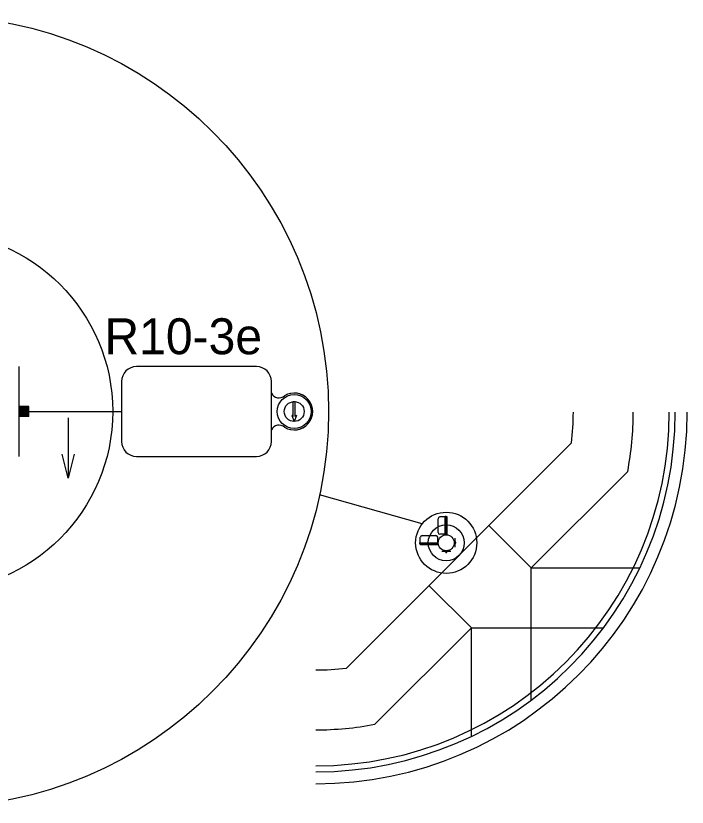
# Model space of a CAD drawing. Extents: x 1695551 to 1695718, y 544410 to 544516.
# Drawn here: x 1695680.98 to 1695694.99, y 544457.81 to 544474.32 of the extents above; entities that cross this region are included whole.
import ezdxf

# ---------------------------------------------------------------- set-up
doc = ezdxf.new("R2010")
doc.units = 0
doc.layers.add('T_Drafting', color=7, linetype='Continuous')

msp = doc.modelspace()

# ---------------------------------------------------------------- linework, layer by layer
at = {"layer": 'T_Drafting'}
for p, q in [((1695681.044, 544467.004), (1695681.044, 544465.129)), ((1695686.003, 544467.004), (1695683.499, 544467.004)), ((1695683.186, 544466.691), (1695683.186, 544465.441)), ((1695686.315, 544465.441), (1695686.315, 544466.691)), ((1695686.771, 544466.273), (1695686.809, 544466.273)), ((1695686.771, 544465.96), (1695686.771, 544466.273)), ((1695686.809, 544465.96), (1695686.809, 544466.273)), ((1695681.252, 544466.171), (1695681.044, 544466.171)), ((1695681.044, 544465.963), (1695681.251, 544466.171)), ((1695681.044, 544465.967), (1695681.248, 544466.171)), ((1695681.044, 544465.97), (1695681.244, 544466.171)), ((1695681.044, 544465.974), (1695681.241, 544466.171)), ((1695681.044, 544465.977), (1695681.237, 544466.171)), ((1695681.044, 544465.981), (1695681.234, 544466.171)), ((1695681.044, 544465.984), (1695681.23, 544466.171)), ((1695681.044, 544465.988), (1695681.227, 544466.171)), ((1695681.044, 544465.991), (1695681.223, 544466.171)), ((1695681.044, 544465.995), (1695681.22, 544466.171)), ((1695681.044, 544465.998), (1695681.216, 544466.171)), ((1695681.044, 544466.002), (1695681.213, 544466.171)), ((1695681.044, 544466.005), (1695681.209, 544466.171)), ((1695681.044, 544466.009), (1695681.205, 544466.171)), ((1695681.044, 544466.013), (1695681.202, 544466.171)), ((1695681.044, 544466.016), (1695681.198, 544466.171)), ((1695681.044, 544466.02), (1695681.195, 544466.171)), ((1695681.044, 544466.023), (1695681.191, 544466.171)), ((1695681.044, 544466.027), (1695681.188, 544466.171)), ((1695681.044, 544466.03), (1695681.184, 544466.171)), ((1695681.044, 544466.034), (1695681.181, 544466.171)), ((1695681.044, 544466.037), (1695681.177, 544466.171)), ((1695681.044, 544466.041), (1695681.174, 544466.171)), ((1695681.044, 544466.044), (1695681.17, 544466.171)), ((1695681.044, 544466.048), (1695681.167, 544466.171)), ((1695681.044, 544466.051), (1695681.163, 544466.171)), ((1695681.044, 544466.055), (1695681.16, 544466.171)), ((1695681.044, 544466.058), (1695681.156, 544466.171)), ((1695681.044, 544466.062), (1695681.152, 544466.171)), ((1695681.044, 544466.066), (1695681.149, 544466.171)), ((1695681.044, 544466.069), (1695681.145, 544466.171)), ((1695681.044, 544466.073), (1695681.142, 544466.171)), ((1695681.044, 544466.076), (1695681.138, 544466.171)), ((1695681.044, 544466.08), (1695681.135, 544466.171)), ((1695681.044, 544466.083), (1695681.131, 544466.171)), ((1695681.044, 544466.087), (1695681.128, 544466.171)), ((1695681.044, 544466.09), (1695681.124, 544466.171)), ((1695681.044, 544466.094), (1695681.121, 544466.171)), ((1695681.044, 544466.097), (1695681.117, 544466.171)), ((1695681.044, 544466.101), (1695681.114, 544466.171)), ((1695681.044, 544466.104), (1695681.11, 544466.171)), ((1695681.044, 544466.108), (1695681.106, 544466.171)), ((1695681.044, 544466.112), (1695681.103, 544466.171)), ((1695681.044, 544466.115), (1695681.099, 544466.171)), ((1695681.044, 544466.119), (1695681.096, 544466.171)), ((1695681.044, 544466.122), (1695681.092, 544466.171)), ((1695681.044, 544466.126), (1695681.089, 544466.171)), ((1695681.044, 544466.129), (1695681.085, 544466.171)), ((1695681.044, 544466.133), (1695681.082, 544466.171)), ((1695681.044, 544466.136), (1695681.078, 544466.171)), ((1695681.044, 544466.14), (1695681.075, 544466.171)), ((1695681.044, 544466.143), (1695681.071, 544466.171)), ((1695681.044, 544466.147), (1695681.068, 544466.171)), ((1695681.044, 544466.15), (1695681.064, 544466.171)), ((1695681.044, 544466.154), (1695681.061, 544466.171)), ((1695681.044, 544466.157), (1695681.057, 544466.171)), ((1695681.044, 544466.161), (1695681.053, 544466.171)), ((1695681.044, 544466.165), (1695681.05, 544466.171)), ((1695681.044, 544466.168), (1695681.046, 544466.171)), ((1695681.047, 544465.962), (1695681.252, 544466.168)), ((1695681.05, 544465.962), (1695681.252, 544466.164)), ((1695681.054, 544465.962), (1695681.252, 544466.161)), ((1695681.057, 544465.962), (1695681.252, 544466.157)), ((1695681.061, 544465.962), (1695681.252, 544466.154)), ((1695681.064, 544465.962), (1695681.252, 544466.15)), ((1695681.068, 544465.962), (1695681.252, 544466.147)), ((1695681.071, 544465.962), (1695681.252, 544466.143)), ((1695681.075, 544465.962), (1695681.252, 544466.14)), ((1695681.078, 544465.962), (1695681.252, 544466.136)), ((1695681.082, 544465.962), (1695681.252, 544466.132)), ((1695681.086, 544465.962), (1695681.252, 544466.129)), ((1695681.089, 544465.962), (1695681.252, 544466.125)), ((1695681.093, 544465.962), (1695681.252, 544466.122)), ((1695681.096, 544465.962), (1695681.252, 544466.118)), ((1695681.1, 544465.962), (1695681.252, 544466.115)), ((1695681.103, 544465.962), (1695681.252, 544466.111)), ((1695681.107, 544465.962), (1695681.252, 544466.108)), ((1695681.11, 544465.962), (1695681.252, 544466.104)), ((1695681.114, 544465.962), (1695681.252, 544466.101)), ((1695681.117, 544465.962), (1695681.252, 544466.097)), ((1695681.121, 544465.962), (1695681.252, 544466.094)), ((1695681.124, 544465.962), (1695681.252, 544466.09)), ((1695681.128, 544465.962), (1695681.252, 544466.086)), ((1695681.132, 544465.962), (1695681.252, 544466.083)), ((1695681.252, 544465.962), (1695681.252, 544466.171)), ((1695681.252, 544465.962), (1695681.044, 544465.962)), ((1695681.135, 544465.962), (1695681.252, 544466.079)), ((1695681.139, 544465.962), (1695681.252, 544466.076)), ((1695681.142, 544465.962), (1695681.252, 544466.072)), ((1695681.146, 544465.962), (1695681.252, 544466.069)), ((1695681.149, 544465.962), (1695681.252, 544466.065)), ((1695681.153, 544465.962), (1695681.252, 544466.062)), ((1695681.156, 544465.962), (1695681.252, 544466.058)), ((1695681.16, 544465.962), (1695681.252, 544466.055)), ((1695681.163, 544465.962), (1695681.252, 544466.051)), ((1695681.167, 544465.962), (1695681.252, 544466.048)), ((1695681.17, 544465.962), (1695681.252, 544466.044)), ((1695681.174, 544465.962), (1695681.252, 544466.041)), ((1695681.177, 544465.962), (1695681.252, 544466.037)), ((1695681.181, 544465.962), (1695681.252, 544466.033)), ((1695681.185, 544465.962), (1695681.252, 544466.03)), ((1695681.188, 544465.962), (1695681.252, 544466.026)), ((1695681.192, 544465.962), (1695681.252, 544466.023)), ((1695681.195, 544465.962), (1695681.252, 544466.019)), ((1695681.199, 544465.962), (1695681.252, 544466.016)), ((1695681.202, 544465.962), (1695681.252, 544466.012)), ((1695681.206, 544465.962), (1695681.252, 544466.009)), ((1695681.209, 544465.962), (1695681.252, 544466.005)), ((1695681.213, 544465.962), (1695681.252, 544466.002)), ((1695681.216, 544465.962), (1695681.252, 544465.998)), ((1695681.22, 544465.962), (1695681.252, 544465.995)), ((1695681.223, 544465.962), (1695681.252, 544465.991)), ((1695681.227, 544465.962), (1695681.252, 544465.987)), ((1695681.231, 544465.962), (1695681.252, 544465.984)), ((1695681.234, 544465.962), (1695681.252, 544465.98)), ((1695681.238, 544465.962), (1695681.252, 544465.977)), ((1695681.241, 544465.962), (1695681.252, 544465.973)), ((1695681.245, 544465.962), (1695681.252, 544465.97)), ((1695681.248, 544465.962), (1695681.252, 544465.966)), ((1695681.252, 544466.066), (1695683.186, 544466.066)), ((1695681.252, 544465.962), (1695681.252, 544465.963)), ((1695682.071, 544465.933), (1695682.071, 544464.675)), ((1695686.74, 544465.985), (1695686.79, 544465.858)), ((1695686.771, 544465.96), (1695686.74, 544465.985)), ((1695686.84, 544465.985), (1695686.79, 544465.858)), ((1695686.84, 544465.985), (1695686.809, 544465.96)), ((1695687.878, 544460.713), (1695692.576, 544465.411)), ((1695683.499, 544465.129), (1695686.003, 544465.129)), ((1695691.736, 544462.803), (1695693.748, 544464.815)), ((1695689.463, 544463.725), (1695687.321, 544464.325)), ((1695689.791, 544463.543), (1695689.791, 544463.83)), ((1695689.943, 544463.868), (1695689.829, 544463.868)), ((1695689.943, 544463.494), (1695689.943, 544463.879)), ((1695689.962, 544463.879), (1695689.943, 544463.879)), ((1695689.962, 544463.494), (1695689.962, 544463.879)), ((1695689.981, 544463.868), (1695689.962, 544463.868)), ((1695689.981, 544463.505), (1695689.981, 544463.868)), ((1695690.852, 544463.687), (1695691.736, 544462.803)), ((1695689.421, 544463.327), (1695689.421, 544463.442)), ((1695689.459, 544463.479), (1695689.746, 544463.479)), ((1695689.784, 544463.327), (1695689.784, 544463.442)), ((1695689.943, 544463.505), (1695689.829, 544463.505)), ((1695689.962, 544463.494), (1695689.943, 544463.494)), ((1695689.981, 544463.505), (1695689.962, 544463.505)), ((1695689.41, 544463.327), (1695689.795, 544463.327)), ((1695689.41, 544463.308), (1695689.41, 544463.327)), ((1695689.41, 544463.308), (1695689.795, 544463.308)), ((1695689.421, 544463.29), (1695689.421, 544463.308)), ((1695689.421, 544463.29), (1695689.784, 544463.29)), ((1695689.784, 544463.29), (1695689.784, 544463.308)), ((1695689.795, 544463.308), (1695689.795, 544463.327)), ((1695690.141, 544463.421), (1695690.141, 544463.233)), ((1695690.162, 544463.338), (1695690.141, 544463.338)), ((1695690.141, 544463.317), (1695690.162, 544463.338)), ((1695690.141, 544463.317), (1695690.161, 544463.338)), ((1695690.141, 544463.317), (1695690.161, 544463.338)), ((1695690.141, 544463.318), (1695690.161, 544463.338)), ((1695690.141, 544463.318), (1695690.16, 544463.338)), ((1695690.141, 544463.319), (1695690.16, 544463.338)), ((1695690.141, 544463.319), (1695690.16, 544463.338)), ((1695690.141, 544463.319), (1695690.159, 544463.338)), ((1695690.141, 544463.32), (1695690.159, 544463.338)), ((1695690.141, 544463.32), (1695690.159, 544463.338)), ((1695690.141, 544463.32), (1695690.158, 544463.338)), ((1695690.141, 544463.321), (1695690.158, 544463.338)), ((1695690.141, 544463.321), (1695690.158, 544463.338)), ((1695690.141, 544463.321), (1695690.157, 544463.338)), ((1695690.141, 544463.322), (1695690.157, 544463.338)), ((1695690.141, 544463.322), (1695690.156, 544463.338)), ((1695690.141, 544463.322), (1695690.156, 544463.338)), ((1695690.141, 544463.323), (1695690.156, 544463.338)), ((1695690.141, 544463.323), (1695690.155, 544463.338)), ((1695690.141, 544463.323), (1695690.155, 544463.338)), ((1695690.141, 544463.324), (1695690.155, 544463.338)), ((1695690.141, 544463.324), (1695690.154, 544463.338)), ((1695690.141, 544463.325), (1695690.154, 544463.338)), ((1695690.141, 544463.325), (1695690.154, 544463.338)), ((1695690.141, 544463.325), (1695690.153, 544463.338)), ((1695690.141, 544463.326), (1695690.153, 544463.338)), ((1695690.141, 544463.326), (1695690.153, 544463.338)), ((1695690.141, 544463.326), (1695690.152, 544463.338)), ((1695690.141, 544463.327), (1695690.152, 544463.338)), ((1695690.141, 544463.327), (1695690.152, 544463.338)), ((1695690.141, 544463.327), (1695690.151, 544463.338)), ((1695690.141, 544463.328), (1695690.151, 544463.338)), ((1695690.141, 544463.328), (1695690.15, 544463.338)), ((1695690.141, 544463.328), (1695690.15, 544463.338)), ((1695690.141, 544463.329), (1695690.15, 544463.338)), ((1695690.141, 544463.329), (1695690.149, 544463.338)), ((1695690.141, 544463.329), (1695690.149, 544463.338)), ((1695690.141, 544463.33), (1695690.149, 544463.338)), ((1695690.141, 544463.33), (1695690.148, 544463.338)), ((1695690.141, 544463.331), (1695690.148, 544463.338)), ((1695690.141, 544463.331), (1695690.148, 544463.338)), ((1695690.141, 544463.331), (1695690.147, 544463.338)), ((1695690.141, 544463.332), (1695690.147, 544463.338)), ((1695690.141, 544463.332), (1695690.147, 544463.338)), ((1695690.141, 544463.332), (1695690.146, 544463.338)), ((1695690.141, 544463.333), (1695690.146, 544463.338)), ((1695690.141, 544463.333), (1695690.146, 544463.338)), ((1695690.141, 544463.333), (1695690.145, 544463.338)), ((1695690.141, 544463.334), (1695690.145, 544463.338)), ((1695690.141, 544463.334), (1695690.144, 544463.338)), ((1695690.141, 544463.334), (1695690.144, 544463.338)), ((1695690.141, 544463.335), (1695690.144, 544463.338)), ((1695690.141, 544463.335), (1695690.143, 544463.338)), ((1695690.141, 544463.335), (1695690.143, 544463.338)), ((1695690.141, 544463.336), (1695690.143, 544463.338)), ((1695690.141, 544463.336), (1695690.142, 544463.338)), ((1695690.141, 544463.337), (1695690.142, 544463.338)), ((1695690.141, 544463.337), (1695690.142, 544463.338)), ((1695690.141, 544463.337), (1695690.141, 544463.338)), ((1695690.141, 544463.317), (1695690.162, 544463.337)), ((1695690.162, 544463.317), (1695690.141, 544463.317)), ((1695690.142, 544463.317), (1695690.162, 544463.337)), ((1695690.142, 544463.317), (1695690.162, 544463.337)), ((1695690.142, 544463.317), (1695690.162, 544463.336)), ((1695690.143, 544463.317), (1695690.162, 544463.336)), ((1695690.143, 544463.317), (1695690.162, 544463.335)), ((1695690.143, 544463.317), (1695690.162, 544463.335)), ((1695690.144, 544463.317), (1695690.162, 544463.335)), ((1695690.144, 544463.317), (1695690.162, 544463.334)), ((1695690.144, 544463.317), (1695690.162, 544463.334)), ((1695690.145, 544463.317), (1695690.162, 544463.334)), ((1695690.145, 544463.317), (1695690.162, 544463.333)), ((1695690.146, 544463.317), (1695690.162, 544463.333)), ((1695690.146, 544463.317), (1695690.162, 544463.333)), ((1695690.146, 544463.317), (1695690.162, 544463.332)), ((1695690.147, 544463.317), (1695690.162, 544463.332)), ((1695690.147, 544463.317), (1695690.162, 544463.332)), ((1695690.147, 544463.317), (1695690.162, 544463.331)), ((1695690.148, 544463.317), (1695690.162, 544463.331)), ((1695690.148, 544463.317), (1695690.162, 544463.331)), ((1695690.148, 544463.317), (1695690.162, 544463.33)), ((1695690.149, 544463.317), (1695690.162, 544463.33)), ((1695690.149, 544463.317), (1695690.162, 544463.329)), ((1695690.149, 544463.317), (1695690.162, 544463.329)), ((1695690.15, 544463.317), (1695690.162, 544463.329)), ((1695690.15, 544463.317), (1695690.162, 544463.328)), ((1695690.151, 544463.317), (1695690.162, 544463.328)), ((1695690.151, 544463.317), (1695690.162, 544463.328)), ((1695690.151, 544463.317), (1695690.162, 544463.327)), ((1695690.152, 544463.317), (1695690.162, 544463.327)), ((1695690.152, 544463.317), (1695690.162, 544463.327)), ((1695690.152, 544463.317), (1695690.162, 544463.326)), ((1695690.153, 544463.317), (1695690.162, 544463.326)), ((1695690.153, 544463.317), (1695690.162, 544463.326)), ((1695690.153, 544463.317), (1695690.162, 544463.325)), ((1695690.154, 544463.317), (1695690.162, 544463.325)), ((1695690.154, 544463.317), (1695690.162, 544463.325)), ((1695690.154, 544463.317), (1695690.162, 544463.324)), ((1695690.155, 544463.317), (1695690.162, 544463.324)), ((1695690.155, 544463.317), (1695690.162, 544463.323)), ((1695690.155, 544463.317), (1695690.162, 544463.323)), ((1695690.156, 544463.317), (1695690.162, 544463.323)), ((1695690.156, 544463.317), (1695690.162, 544463.322)), ((1695690.157, 544463.317), (1695690.162, 544463.322)), ((1695690.157, 544463.317), (1695690.162, 544463.322)), ((1695690.157, 544463.317), (1695690.162, 544463.321)), ((1695690.158, 544463.317), (1695690.162, 544463.321)), ((1695690.158, 544463.317), (1695690.162, 544463.321)), ((1695690.158, 544463.317), (1695690.162, 544463.32)), ((1695690.159, 544463.317), (1695690.162, 544463.32)), ((1695690.159, 544463.317), (1695690.162, 544463.32)), ((1695690.159, 544463.317), (1695690.162, 544463.319)), ((1695690.16, 544463.317), (1695690.162, 544463.319)), ((1695690.16, 544463.317), (1695690.162, 544463.319)), ((1695690.16, 544463.317), (1695690.162, 544463.318)), ((1695690.161, 544463.317), (1695690.162, 544463.318)), ((1695690.161, 544463.317), (1695690.162, 544463.317)), ((1695690.161, 544463.317), (1695690.162, 544463.317)), ((1695690.162, 544463.317), (1695690.162, 544463.338)), ((1695690.162, 544463.317), (1695690.162, 544463.317)), ((1695690.056, 544463.148), (1695689.868, 544463.148)), ((1695689.951, 544463.127), (1695689.951, 544463.148)), ((1695689.951, 544463.127), (1695689.972, 544463.148)), ((1695689.951, 544463.128), (1695689.972, 544463.148)), ((1695689.951, 544463.128), (1695689.971, 544463.148)), ((1695689.951, 544463.128), (1695689.971, 544463.148)), ((1695689.951, 544463.129), (1695689.971, 544463.148)), ((1695689.951, 544463.129), (1695689.97, 544463.148)), ((1695689.951, 544463.129), (1695689.97, 544463.148)), ((1695689.951, 544463.13), (1695689.97, 544463.148)), ((1695689.951, 544463.13), (1695689.969, 544463.148)), ((1695689.951, 544463.13), (1695689.969, 544463.148)), ((1695689.951, 544463.131), (1695689.969, 544463.148)), ((1695689.951, 544463.131), (1695689.968, 544463.148)), ((1695689.951, 544463.131), (1695689.968, 544463.148)), ((1695689.951, 544463.132), (1695689.968, 544463.148)), ((1695689.951, 544463.132), (1695689.967, 544463.148)), ((1695689.951, 544463.133), (1695689.967, 544463.148)), ((1695689.951, 544463.133), (1695689.966, 544463.148)), ((1695689.951, 544463.133), (1695689.966, 544463.148)), ((1695689.951, 544463.134), (1695689.966, 544463.148)), ((1695689.951, 544463.134), (1695689.965, 544463.148)), ((1695689.951, 544463.134), (1695689.965, 544463.148)), ((1695689.951, 544463.135), (1695689.965, 544463.148)), ((1695689.951, 544463.135), (1695689.964, 544463.148)), ((1695689.951, 544463.135), (1695689.964, 544463.148)), ((1695689.951, 544463.136), (1695689.964, 544463.148)), ((1695689.951, 544463.136), (1695689.963, 544463.148)), ((1695689.951, 544463.136), (1695689.963, 544463.148)), ((1695689.951, 544463.137), (1695689.963, 544463.148)), ((1695689.951, 544463.137), (1695689.962, 544463.148)), ((1695689.951, 544463.138), (1695689.962, 544463.148)), ((1695689.951, 544463.138), (1695689.962, 544463.148)), ((1695689.951, 544463.138), (1695689.961, 544463.148)), ((1695689.951, 544463.139), (1695689.961, 544463.148)), ((1695689.951, 544463.139), (1695689.96, 544463.148)), ((1695689.951, 544463.139), (1695689.96, 544463.148)), ((1695689.951, 544463.14), (1695689.96, 544463.148)), ((1695689.951, 544463.14), (1695689.959, 544463.148)), ((1695689.951, 544463.14), (1695689.959, 544463.148)), ((1695689.951, 544463.141), (1695689.959, 544463.148)), ((1695689.951, 544463.141), (1695689.958, 544463.148)), ((1695689.951, 544463.141), (1695689.958, 544463.148)), ((1695689.951, 544463.142), (1695689.958, 544463.148)), ((1695689.951, 544463.142), (1695689.957, 544463.148)), ((1695689.951, 544463.142), (1695689.957, 544463.148)), ((1695689.951, 544463.143), (1695689.957, 544463.148)), ((1695689.951, 544463.143), (1695689.956, 544463.148)), ((1695689.951, 544463.144), (1695689.956, 544463.148)), ((1695689.951, 544463.144), (1695689.956, 544463.148)), ((1695689.951, 544463.144), (1695689.955, 544463.148)), ((1695689.951, 544463.145), (1695689.955, 544463.148)), ((1695689.951, 544463.145), (1695689.954, 544463.148)), ((1695689.951, 544463.145), (1695689.954, 544463.148)), ((1695689.951, 544463.146), (1695689.954, 544463.148)), ((1695689.951, 544463.146), (1695689.953, 544463.148)), ((1695689.951, 544463.146), (1695689.953, 544463.148)), ((1695689.951, 544463.147), (1695689.953, 544463.148)), ((1695689.951, 544463.147), (1695689.952, 544463.148)), ((1695689.951, 544463.147), (1695689.952, 544463.148)), ((1695689.951, 544463.148), (1695689.952, 544463.148)), ((1695689.951, 544463.127), (1695689.972, 544463.127)), ((1695689.952, 544463.127), (1695689.972, 544463.148)), ((1695689.952, 544463.127), (1695689.972, 544463.147)), ((1695689.952, 544463.127), (1695689.972, 544463.147)), ((1695689.953, 544463.127), (1695689.972, 544463.147)), ((1695689.953, 544463.127), (1695689.972, 544463.146)), ((1695689.953, 544463.127), (1695689.972, 544463.146)), ((1695689.954, 544463.127), (1695689.972, 544463.146)), ((1695689.954, 544463.127), (1695689.972, 544463.145)), ((1695689.954, 544463.127), (1695689.972, 544463.145)), ((1695689.955, 544463.127), (1695689.972, 544463.145)), ((1695689.955, 544463.127), (1695689.972, 544463.144)), ((1695689.956, 544463.127), (1695689.972, 544463.144)), ((1695689.956, 544463.127), (1695689.972, 544463.143)), ((1695689.956, 544463.127), (1695689.972, 544463.143)), ((1695689.957, 544463.127), (1695689.972, 544463.143)), ((1695689.957, 544463.127), (1695689.972, 544463.142)), ((1695689.957, 544463.127), (1695689.972, 544463.142)), ((1695689.958, 544463.127), (1695689.972, 544463.142)), ((1695689.958, 544463.127), (1695689.972, 544463.141)), ((1695689.958, 544463.127), (1695689.972, 544463.141)), ((1695689.959, 544463.127), (1695689.972, 544463.141)), ((1695689.959, 544463.127), (1695689.972, 544463.14)), ((1695689.959, 544463.127), (1695689.972, 544463.14)), ((1695689.96, 544463.127), (1695689.972, 544463.14)), ((1695689.96, 544463.127), (1695689.972, 544463.139)), ((1695689.96, 544463.127), (1695689.972, 544463.139)), ((1695689.961, 544463.127), (1695689.972, 544463.139)), ((1695689.961, 544463.127), (1695689.972, 544463.138)), ((1695689.962, 544463.127), (1695689.972, 544463.138)), ((1695689.962, 544463.127), (1695689.972, 544463.137)), ((1695689.962, 544463.127), (1695689.972, 544463.137)), ((1695689.963, 544463.127), (1695689.972, 544463.137)), ((1695689.963, 544463.127), (1695689.972, 544463.136)), ((1695689.963, 544463.127), (1695689.972, 544463.136)), ((1695689.964, 544463.127), (1695689.972, 544463.136)), ((1695689.964, 544463.127), (1695689.972, 544463.135)), ((1695689.964, 544463.127), (1695689.972, 544463.135)), ((1695689.965, 544463.127), (1695689.972, 544463.135)), ((1695689.965, 544463.127), (1695689.972, 544463.134)), ((1695689.965, 544463.127), (1695689.972, 544463.134)), ((1695689.966, 544463.127), (1695689.972, 544463.134)), ((1695689.966, 544463.127), (1695689.972, 544463.133)), ((1695689.966, 544463.127), (1695689.972, 544463.133)), ((1695689.967, 544463.127), (1695689.972, 544463.133)), ((1695689.967, 544463.127), (1695689.972, 544463.132)), ((1695689.968, 544463.127), (1695689.972, 544463.132)), ((1695689.968, 544463.127), (1695689.972, 544463.131)), ((1695689.968, 544463.127), (1695689.972, 544463.131)), ((1695689.969, 544463.127), (1695689.972, 544463.131)), ((1695689.969, 544463.127), (1695689.972, 544463.13)), ((1695689.969, 544463.127), (1695689.972, 544463.13)), ((1695689.97, 544463.127), (1695689.972, 544463.13)), ((1695689.97, 544463.127), (1695689.972, 544463.129)), ((1695689.97, 544463.127), (1695689.972, 544463.129)), ((1695689.971, 544463.127), (1695689.972, 544463.129)), ((1695689.971, 544463.127), (1695689.972, 544463.128)), ((1695689.971, 544463.127), (1695689.972, 544463.128)), ((1695689.972, 544463.127), (1695689.972, 544463.148)), ((1695689.972, 544463.127), (1695689.972, 544463.128)), ((1695689.972, 544463.127), (1695689.972, 544463.127)), ((1695691.736, 544460.047), (1695691.736, 544462.803)), ((1695691.736, 544462.803), (1695694, 544462.803)), ((1695689.602, 544462.437), (1695690.486, 544461.553)), ((1695688.474, 544459.541), (1695690.486, 544461.553)), ((1695690.486, 544461.553), (1695693.242, 544461.553)), ((1695690.486, 544459.289), (1695690.486, 544461.553))]:
    msp.add_line(p, q, dxfattribs=at)
msp.add_lwpolyline([(1695682.196, 544465.175), (1695682.071, 544464.675), (1695681.946, 544465.175)], dxfattribs=at)
for centre, radius in [((1695679.252, 544466.066), 8.254), ((1695679.252, 544466.066), 3.75), ((1695686.79, 544466.066), 0.354), ((1695686.79, 544466.066), 0.208), ((1695689.962, 544463.327), 0.638), ((1695689.962, 544463.327), 0.375), ((1695689.962, 544463.327), 0.167)]:
    msp.add_circle(centre, radius, dxfattribs=at)
for centre, radius, start, end in [((1695683.499, 544466.691), 0.312, 90, 180), ((1695686.003, 544466.691), 0.312, 0, 90), ((1695686.473, 544466.526), 0.175, 205.1956, 311.8028), ((1695686.79, 544466.066), 0.385, 238.7402, 121.2598), ((1695686.79, 544466.066), 0.385, 42.5066, 121.2598), ((1695687.239, 544466.05), 7.5, 270, 0), ((1695687.239, 544466.05), 7.75, 270, 0), ((1695687.239, 544466.05), 7.375, 270, 0), ((1695687.239, 544466.05), 5.375, 353.1741, 360), ((1695687.239, 544466.05), 6.625, 349.2603, 0), ((1695686.473, 544465.607), 0.175, 48.1972, 154.8044), ((1695686.79, 544466.066), 0.385, 238.7402, 317.4934), ((1695683.499, 544465.441), 0.312, 180, 270), ((1695686.003, 544465.441), 0.312, 270, 0), ((1695689.829, 544463.83), 0.0375, 90, 180), ((1695689.459, 544463.442), 0.0375, 90, 180), ((1695689.746, 544463.442), 0.0375, 360, 90), ((1695689.829, 544463.543), 0.0375, 180, 270), ((1695687.239, 544466.05), 5.375, 270, 276.8259), ((1695687.239, 544466.05), 6.625, 270, 280.7397)]:
    msp.add_arc(centre, radius, start, end, dxfattribs=at)

# ---------------------------------------------------------------- texts
msp.add_text('R10-3e', height=0.75, dxfattribs=at).set_placement((1695682.83, 544467.261))

doc.saveas('drawing.dxf')
